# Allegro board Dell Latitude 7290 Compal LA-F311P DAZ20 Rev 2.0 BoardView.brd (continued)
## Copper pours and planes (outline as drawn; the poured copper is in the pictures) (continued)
+BL_PWR_SRC on TOP (solid shape): 58.13,133.11 59.02,133.11 59.27,132.85 60.79,132.85 60.96,132.69 60.96,131.8 60.4,131.24 59.08,131.24 58.29,132.03 57.73,132.03 57.71,132.05 57.21,132.05 56.98,132.28 56.58,132.28 56.4,132.46 56.4,133.6 56.67,133.87 57.36,133.87
+BL_PWR_SRC on BOTTOM (solid shape): 60.37,133.28 60.37,132 60.54,131.84 60.54,131.39 60.41,131.27 58.96,131.27 58.84,131.39 58.84,131.81 59.13,132.1 59.13,133.28 59.21,133.36 60.3,133.36
+CHARGER_SRC on TOP (solid shape): 47.05,79.39 48.24,79.39 48.24,76.84 48.45,76.63 50.72,76.63 51.31,76.03 51.31,71.76 49.19,69.63 47.09,69.63 46.77,69.31 46.77,68.74 46.71,68.68 46.27,68.68 46.27,72.81 45.75,73.33 45.75,79.88 45.81,79.95 46.49,79.95
+CHARGER_SRC on BOTTOM (solid shape): 46.95,84.49 47.2,84.38 47.45,84.49 49.48,84.49 49.71,84.26 49.71,81.35 49.44,81.07 48.54,81.07 48.53,81.06 48.31,81.06 48,80.75 48,80.74 47.89,80.63 47.89,79.67 48.23,79.33 48.23,76.95 49.6,75.58 49.6,70.84 49.07,70.3 46.64,70.3 46.41,70.53 46.41,71.98 45.77,72.62 45.77,80.47 46.46,81.16 46.46,81.7 46.48,81.72 47.01,81.72 47.01,81.72 47.01,82.46 47.01,82.47 46.47,82.47 46.46,82.47 46.46,82.91 46.47,82.91 47.01,82.91 47.02,82.92 47.02,83.65 47,83.66 46.48,83.66 46.47,83.67 46.47,84.37 46.58,84.49
+DC_IN on TOP (solid shape): 46.51,121.3 46.51,119.77 46.89,119.39 46.89,118.5 45.36,116.98 45.24,116.98 45.11,117.1 45.11,117.16 44.53,117.74 44.47,117.74 44.22,117.99 44.22,118.12 44.6,118.5 44.6,118.58 44.6,119.31 44.63,119.31 44.63,120.08 44.6,120.08 44.6,120.23 44.63,120.23 44.63,120.99 44.6,120.99 44.6,121.3 44.98,121.68 46.12,121.68
+DC_IN on BOTTOM (solid shape): 46.89,123.67 46.89,121.11 47.33,120.66 47.33,118.5 47.26,118.43 43.13,118.43 42.95,118.48 42.77,118.43 41.82,118.43 41.74,118.5 41.74,119.26 41.81,119.33 42.51,119.33 42.89,119.71 42.89,121.17 43.39,121.68 43.71,121.68 44.37,122.34 44.37,123.63 44.71,123.98 46.57,123.98
+DC_IN on IN3: 41.68,80.4 42.16,80.4 42.72,79.84 42.72,79.22 38.58,75.08 38.58,64.02 35.59,61.03 34.74,61.03 34.57,61.2 34.57,61.72 34.84,61.99 34.98,61.99 37.83,64.83 37.83,76.54
+DC_IN_SS on BOTTOM (solid shape): 52.78,119.04 52.78,117.33 52.63,117.18 49.58,117.18 48.94,116.55 48.94,113.24 48.77,113.07 44.59,113.07 44.42,113.12 44.26,113.07 44.19,113.07 43.89,113.37 43.89,115.4 44.17,115.68 44.17,116.32 44.83,116.98 44.83,117.59 45.01,117.77 47.55,117.77 48.97,119.19 52.63,119.19
+DCIN_JACK on BOTTOM (solid shape): 41.91,121.74 41.93,121.74 41.95,121.72 42.01,121.71 42.06,121.7 42.11,121.69 42.31,121.49 42.31,119.84 42.06,119.58 41.74,119.58 41.49,119.33 41.49,118.44 41.3,118.25 39.27,118.25 39.08,118.06 36.66,118.06 36.47,118.25 36.47,118.82 39.78,118.82 39.78,118.77 39.79,118.71 39.8,118.66 39.83,118.61 39.86,118.57 39.89,118.53 39.93,118.5 39.98,118.47 40.03,118.45 40.08,118.44 40.14,118.44 40.19,118.44 40.24,118.45 40.29,118.47 40.34,118.5 40.38,118.53 40.41,118.57 40.44,118.61 40.47,118.66 40.48,118.71 40.49,118.77 40.49,118.82 40.48,118.87 40.47,118.92 40.44,118.97 40.41,119.02 40.38,119.05 40.34,119.09 40.29,119.11 40.24,119.13 40.19,119.15 40.14,119.15 40.08,119.15 40.03,119.13 39.98,119.11 39.93,119.09 39.89,119.05 39.86,119.02 39.83,118.97 39.8,118.92 39.79,118.87 39.78,118.82 36.47,118.82 36.47,121.4 36.82,121.74 41.84,121.74
+EC_DEBUG_VCC on BOTTOM (solid shape): 290.28,126.58 291.32,126.58 291.4,126.5 291.4,126.26 291.3,126.15 289.98,126.15 289.74,126.39 289.19,126.39 288.84,126.75 288.84,127.41 288.88,127.46 289.41,127.46
+EDP_VDD on TOP (solid shape): 67.97,126.76 67.97,124.92 67.65,124.6 66.7,124.6 66.52,124.78 66.52,125.61 65.86,126.27 65.86,127.71 67.02,127.71
+LCDVDD on TOP (solid shape): 69.81,134.5 69.81,132.66 68.73,131.58 66.25,131.58 66.19,131.52 66.19,130.95 65.95,130.7 65.95,128.03 65.68,127.77 65.68,127.46 65.11,127.46 65.11,126.95 65.68,126.95 65.68,126.69 64.6,126.69 64.41,126.88 64.41,131.14 64.79,131.51 64.79,132.39 64.9,132.5 64.92,132.5 65.47,133.04 65.94,133.04 66.38,133.49 66.38,134.57 66.57,134.76 69.56,134.76
+LCDVDD on BOTTOM (solid shape): 66.38,133.3 66.38,132.03 66.57,131.84 66.57,131.2 66.13,130.76 66.13,129.74 66,129.61 64.79,129.61 64.67,129.74 64.67,131.58 64.92,131.84 65.43,131.84 65.62,132.03 65.62,133.3 65.68,133.36 66.32,133.36
+PBATT on TOP (solid shape): 177.47,58.59 177.47,55.73 177.51,55.69 177.51,55.25 177.46,55.19 175.09,55.19 174.97,55.32 174.97,56.46 174.52,56.91 171.98,56.91 170.79,58.1 170.03,58.1 169.86,58.27 169.86,59.85 170.2,60.19 170.2,60.21 170.78,60.78 175.28,60.78
+PWR_SRC on TOP (solid shape): 178.63,51.09 178.9,51.02 179.16,51.09 183.55,51.09 183.73,50.91 183.73,49.52 183.51,49.3 180.24,49.3 180.08,49.45 180.08,50.21 179.83,50.46 178.36,50.46 178.28,50.53 178.28,50.99 178.39,51.09
+PWR_SRC on TOP (solid shape): 44.54,123.33 44.54,121.93 44.28,121.68 41.89,121.68 41.89,122.24 41.82,122.48 41.64,122.67 41.6,122.74 41.63,122.83 41.81,123.01 43.46,123.01 43.9,123.45 44.41,123.45
+PWR_SRC on TOP (solid shape): 151.34,82.84 151.34,82.3 151.36,82.29 151.82,82.29 151.82,79.83 151.72,79.73 150.74,79.73 149.82,80.64 149.82,81.87 149.73,81.97 149.73,82.24 149.77,82.29 150.28,82.29 150.29,82.29 150.29,82.84 150.29,82.84 150.54,82.84 150.54,82.3 150.55,82.29 151.07,82.29 151.08,82.3 151.08,82.84 151.09,82.84 151.34,82.84
+PWR_SRC on TOP (solid shape): 166.22,54.49 167.04,53.67 170.9,53.67 171.22,53.35 171.22,52.41 170.69,52.41 170.67,52.39 170.65,52.38 170.34,52.03 170.65,51.68 170.67,51.67 170.69,51.65 171.14,51.65 171.17,51.62 171.17,50.19 170.84,49.86 164.74,49.86 164.43,50.18 164.43,50.6 164.34,50.68 161.44,50.68 161.31,50.81 161.31,51.17 161.45,51.3 164.03,51.3 164.26,51.53 164.26,54.52 164.38,54.64 164.38,54.64 164.56,54.82 165.89,54.82
+PWR_SRC on TOP (solid shape): outline of 174 points within 57.94,58.35 75.26,81.54
+PWR_SRC on BOTTOM (solid shape): 181.36,50.94 183.9,50.94 184,50.84 184,49.84 184.25,49.59 184.25,49.54 184.05,49.34 180.16,49.34 179.98,49.52 179.98,50.31 180.62,50.94 181.36,50.94
+PWR_SRC on BOTTOM (solid shape): 39.01,130.57 39.01,129.75 38.75,129.13 39.36,128.85 39.39,128.86 39.74,128.5 42.85,128.5 43.54,127.82 43.54,122.07 43.46,121.99 41.94,121.99 41.84,122.09 41.85,122.12 41.86,122.29 41.81,122.46 41.81,126.31 41.52,126.6 39.3,126.6 39.14,126.76 39.14,127.52 37.87,128.79 37.87,130.5 38.06,130.69 38.89,130.69
+PWR_SRC on BOTTOM (solid shape): outline of 2007 points within 57.44,49.86 169,82.82
+PWR_SRC on IN1: 182.47,49.49 182.32,49.34 173.2,49.34 172.39,50.15 170.97,50.15 170.15,49.34 164.82,49.34 164.36,49.79 164.36,52.77 164.46,52.87 177.52,52.87 177.53,52.86 181.53,52.86 182.47,51.91
+PWR_SRC on IN2: 41.87,122.31 42,122.44 43.33,122.44 44.28,121.49 44.28,120.34 44.16,120.22 43.39,120.22 41.87,121.74
+PWR_SRC on IN2: 57.23,117.18 56.55,117.86 56.55,118.64 56.23,118.95 56.23,119.64 56.59,120 57.55,120 58.14,119.42 58.14,118.57 58.65,118.05 58.65,117.46 58.37,117.18
+PWR_SRC on IN4: 57.2,118.3 58.47,118.3 58.88,117.89 58.88,115.93 58.47,115.53 57.42,115.53 56.84,116.11 56.84,117.95
+PWR_SRC on IN4: 62.42,72.41 62.42,70.5 62.61,70.31 62.61,61 62.32,60.72 60.85,60.72 60.35,61.22 60.35,66.54 59.42,67.47 59.42,69.62 58.6,70.45 58.6,77.89 61.73,81.03 71.7,81.03 71.91,80.83 71.91,78.04 70.55,76.68 63.98,76.68 63.72,76.42 63.72,73.69 62.44,72.41
+PWR_SRC on IN4: 172.33,49.98 171.77,49.93 171.2,49.98 170.98,49.46 170.96,49.38 170.88,49.34 164.54,49.34 164.36,49.52 164.36,51.76 164.68,52.08 177.56,52.08 179.19,50.45 182.33,50.45 182.47,50.3 182.47,49.49 182.32,49.34 172.65,49.34 172.57,49.38 172.56,49.46
+PWR_SRC_AC on TOP (solid shape): outline of 120 points within 43.35,81.94 48.85,86.53
+PWR_SRC_AC on BOTTOM (solid shape): outline of 176 points within 41.37,76.77 46.84,85.78
+REGCTL_PNP10 on TOP (solid shape): 246.58,123.43 246.58,122.08 246.91,121.75 246.91,121.09 246.78,120.97 246.3,120.97 246.18,121.09 246.18,121.52 246.3,121.7 246.25,121.91 246.25,122.24 246.38,122.36 246.38,123.43 246.43,123.48 246.53,123.48
+REGCTL_PNP10 on BOTTOM (solid shape): 252.2,125.35 252.2,124.24 251.65,123.68 250.89,123.68 250.54,124.03 250.54,125.28 250.68,125.42 252.13,125.42
+REGCTL_PNP10 on IN4 (solid shape): 251.66,124.38 251.66,123.64 250.58,122.57 247.86,122.57 247.1,121.8 247.1,121.04 246.91,120.85 246.15,120.85 245.83,121.17 245.83,122.57 247.35,124.08 250.22,124.08 250.8,124.67 251.36,124.67
+RTC_CELL_PCH on TOP (solid shape): outline of 333 points within 119.62,89.76 124.68,97.81
+SDC_IN on TOP (solid shape): 52.35,111.14 52.35,109.48 52.03,109.17 50.25,109.17 50.06,109.36 50.06,109.93 49.87,110.12 48.79,110.12 48.66,109.99 48.66,109.36 47.2,109.36 47.14,109.42 47.14,111.2 47.97,112.02 51.46,112.02
+SDC_IN on TOP (solid shape): 45.64,81.19 46,80.83 46.35,81.19 46.35,81.72 46.9,81.72 47.03,81.6 51.05,81.6 51.33,81.32 51.33,80.38 51.28,80.33 50.69,80.37 50.5,79.81 50.49,79.71 50.4,79.67 47.17,79.67 46.61,80.24 45.16,80.24 45.02,80.38 45.02,81.66 45.08,81.72 45.64,81.72
+SDC_IN on BOTTOM (solid shape): 52.75,116.4 52.75,116.39 52.75,111.71 51.01,109.97 51.01,105.23 47.71,105.23 47.69,105.25 47.69,106.8 47.42,107.07 46.23,107.07 45.74,106.59 45.21,106.59 44.98,106.82 44.98,107.63 45.21,107.86 46,107.86 46.23,108.09 46.23,108.6 45.97,108.85 44.91,108.85 44.7,108.65 44.04,108.65 44.04,109.18 44.12,109.26 45.83,109.26 46.06,109.48 46.06,110.06 46.44,110.44 46.44,111.2 46.23,111.42 46.23,112.32 46.32,112.41 48.73,112.41 49.31,112.98 49.31,116.53 49.33,116.56 52.75,116.56
+SDC_IN on IN3: 45.15,78.7 42.49,81.36 42.49,90.5 42.77,90.86 42.62,91.3 42.58,91.37 42.62,91.45 42.78,91.89 42.49,92.25 42.49,95.67 42.58,95.96 42.49,96.24 42.49,99.5 42.52,99.51 42.83,99.83 42.75,100.26 42.85,100.6 42.69,100.91 42.75,101.31 42.49,101.61 42.49,107.98 42.53,108.06 42.61,108.08 43.18,108.56 42.61,109.03 42.53,109.05 42.49,109.13 42.49,109.38 43.23,110.12 43.29,110.1 43.29,110.09 43.31,110.05 43.29,110.01 43.28,110.01 43.55,109.16 43.98,109.94 43.96,110.01 43.99,110.07 44.13,110.41 43.97,110.82 44,110.89 45.33,112.21 45.35,112.21 45.67,112.34 45.83,112.64 45.84,112.69 50.87,112.69 51.55,112.01 51.55,96.06 51.55,96.05 51.55,95.3 51.56,95.3 51.56,91.49 51.85,91.2 51.85,85.48 54.24,83.08 54.24,80.42 52.53,78.7
+SDC_IN on VCC: 46.87,59.7 40.92,65.65 40.92,76.44 38.5,78.86 38.5,80.8 38.74,81.04 48.85,81.04 49.91,82.1 50.33,82.1 51.08,81.35 51.08,75.6 54.63,72.04 54.63,72.03 55.05,71.62 55.05,71.52 52.73,69.2 52.73,59.83 52.6,59.7
+SDREG2 on TOP (solid shape): 279.07,66.88 278.34,66.88 277.77,66.3 277.77,66.23 277.72,66.18 276.96,66.18 276.88,66.25 276.88,66.33 276.93,66.38 277.09,66.38 277.95,67.24 279.07,67.24
+TBT_SVR_IND on BOTTOM (solid shape): 23.25,109.88 23.25,107.64 23.19,107.46 23.24,107.28 23.25,107.27 23.25,107.18 23.35,107.07 23.35,106.92 23.7,106.58 23.7,105.83 23.72,105.8 23.72,105.8 24.06,105.45 24.06,104.54 24.11,104.5 24.11,104.24 24.03,104.15 23.97,104.15 23.93,104.13 23.92,104.13 23.87,104.09 23.79,104 23.79,103.85 23.74,103.8 23.52,103.8 23.44,103.87 23.44,104.05 23.37,104.13 23.37,104.58 23.08,104.86 22.68,104.86 22.36,105.18 22.36,106.06 22.23,106.18 21.74,106.18 21.61,106.31 21.61,109.89 21.72,109.99 23.14,109.99
+TBTA_VBUS on TOP (solid shape): 23.36,116.7 23.36,112.79 23.22,112.66 20.73,112.66 19.52,113.87 16.79,113.87 16.41,114.25 16.41,116.6 16.72,116.91 23.14,116.91
+TBTA_VBUS on TOP (solid shape): 7.29,108.57 8.38,108.57 8.47,108.66 9.76,108.66 9.85,108.57 9.85,108.24 9.78,108.16 8.43,108.16 8.36,108.24 7.16,108.24 7.09,108.16 6.4,108.16 6.27,108.29 6.27,108.67 6.45,108.85 7.01,108.85
+TBTA_VBUS on TOP (solid shape): 7.14,106.06 8.38,106.06 8.47,106.14 9.5,106.14 9.57,106.07 9.57,105.73 9.5,105.65 8.43,105.65 8.34,105.74 7.18,105.74 6.88,105.45 6.42,105.45 6.3,105.57 6.3,106.03 6.42,106.16 7.03,106.16
+TBTA_VBUS on BOTTOM (solid shape): 9.67,105.88 9.98,105.88 10.06,105.8 10.06,104.92 9.86,104.72 9.61,104.72 8.49,105.84 8.49,106.07 8.55,106.13 9.43,106.13
+TBTA_VBUS on IN2: 7.77,109.97 7.78,110.01 7.78,110.84 7.77,110.88 7.77,112.91 8.79,113.93 10.76,113.93 13.11,113.83 14.75,115.51 15.84,116.6 21.61,116.6 22.19,116.03 22.19,113.42 21.8,113.04 18.69,113.04 15.45,109.8 11.33,109.8 11,109.48 10.99,109.47 10.87,109.39 10.79,109.27 10.79,109.26 10.63,109.1 10.63,108.25 10.54,108.01 10.63,107.78 10.63,105.87 10.18,105.42 6.44,105.42 6.32,105.54 6.32,106 6.44,106.12 7.07,106.12 7.26,106.31 7.26,107.96 7.07,108.15 6.5,108.15 6.32,108.33 6.32,108.99 6.56,109.23 7.2,109.23 7.77,109.8
+TBTA_VBUS on VCC: 7.62,105.29 7.5,105.42 6.48,105.42 6.35,105.55 6.17,105.55 6.17,111.63 5.19,113.04 3.52,112.64 1.42,112.64 1.42,114.59 2.27,115.01 2.62,115.9 2.62,117.08 9.73,117.08 9.73,116.5 12.05,114.18 14.37,116.5 14.37,117.08 22.12,117.08 22.12,116.87 22.38,116.62 22.38,114.42 22.02,114.06 20.87,114.06 16.66,109.84 16.66,108.57 16.43,108.34 12.75,108.34 9.7,105.29
+TBTA_VBUS_1 on TOP (solid shape): 29.11,121.18 29.11,118.86 29.41,118.56 29.41,116.28 29.96,116.28 29.96,115.83 29.42,115.83 29.42,115.08 29.96,115.08 29.96,114.63 29.42,114.63 29.42,112.97 29.36,112.91 27.03,112.91 26.78,112.66 25.87,112.66 25.76,112.78 25.76,113.38 25.63,113.51 24.11,113.51 24.03,113.59 24.03,116.69 24.2,116.86 25.54,116.86 26.12,117.44 26.12,121.04 26.31,121.23 29.06,121.23
+TBTA_VBUS_1 on BOTTOM (solid shape): 29.82,85.78 29.82,84.97 29.83,84.93 29.85,84.88 29.85,84.63 30.6,83.88 30.6,83.36 30.57,83.32 30.38,83.32 30.25,83.2 30.25,82.92 30.14,82.81 29.87,82.81 29.81,82.88 29.81,83.2 29.68,83.32 29.42,83.32 29.36,83.39 29.36,83.58 29.1,83.84 28.82,83.84 28.12,84.54 28.12,84.68 27.78,85.02 27.76,85.07 27.73,85.11 27.49,85.35 27.49,86.02 27.71,86.24 27.82,86.24 27.82,86.36 27.84,86.37 29.23,86.37
+TBTA_VBUS_1 on BOTTOM (solid shape): 20.31,75.74 20.31,74.06 19.98,73.73 18.06,73.73 17.93,73.86 17.93,73.92 17.61,74.24 16.72,74.24 16.22,74.75 16.22,75.61 19.34,75.61 19.34,75.56 19.36,75.51 19.37,75.46 19.4,75.41 19.43,75.37 19.47,75.34 19.52,75.3 19.57,75.28 19.62,75.27 19.67,75.26 19.72,75.26 19.78,75.27 19.83,75.28 19.87,75.3 19.92,75.34 19.96,75.37 19.99,75.41 20.02,75.46 20.04,75.51 20.05,75.56 20.05,75.61 20.05,75.67 20.04,75.72 20.02,75.77 19.99,75.82 19.96,75.86 19.92,75.89 19.87,75.92 19.83,75.95 19.78,75.96 19.72,75.97 19.67,75.97 19.62,75.96 19.57,75.95 19.52,75.92 19.47,75.89 19.43,75.86 19.4,75.82 19.37,75.77 19.36,75.72 19.34,75.67 19.34,75.61 16.22,75.61 16.22,75.64 16.66,76.08 19.96,76.08
+TBTA_VBUS_1 on IN2: 23.77,75.84 22.45,75.84 22.45,75.84 18.95,75.84 18.72,76.07 17.66,76.07 17.55,75.96 17.55,74.14 20.72,70.97 25.9,70.97 27.46,72.52 27.46,74.08 28,74.62 28.51,74.62 33.97,80.09 33.97,81.99 35.03,83.05 35.03,84.1 34.12,85.01 30.74,85.01 29.13,86.63 27.9,86.63 26.85,85.57 26.85,84.57 25.91,83.63 25.91,82.34 24.74,81.18 24.74,77.23 24.02,76.51 24.02,76.09
+TBTA_VBUS_1 on IN3: 16.08,75.16 11.42,79.82 11.42,94.6 10.5,95.52 10.5,99.46 7.89,102.07 7.89,111.1 10.41,113.62 13.15,113.62 16.61,117.08 24.6,117.08 25.22,117.24 25.7,117.67 28.14,117.67 28.95,116.87 28.95,114.67 26.51,112.23 21.69,112.23 21,111.54 21,109.41 17.44,105.84 17.44,98.25 19.16,96.53 19.16,93.4 18.94,93.17 18.94,92.68 20.25,91.36 20.25,74.39 19.87,74.01 17,74.01 16.08,74.94
+USB_EX2_PWR on TOP (solid shape): 19.65,67.45 19.65,65.35 15.64,65.35 15.33,65.67 15.33,67.19 15.71,67.57 19.52,67.57
+USB_EX2_PWR on BOTTOM (solid shape): 20.09,58.11 20.09,56.4 20.31,56.18 20.31,55.23 20.19,55.12 18.58,55.12 18.25,55.45 18.25,57.92 18.5,58.18 20.03,58.18
+USB_EX2_PWR on IN2: 17.93,64.78 17.93,55.76 18.18,55.51 19.65,55.51 19.96,55.83 19.96,67 19.52,67.45 15.77,67.45 15.33,67 15.33,65.73 15.71,65.35 17.36,65.35
+UZ12_TPM on BOTTOM (solid shape): 162.85,115.96 162.85,115.45 162.84,115.45 162.08,114.69 162.08,112.47 161.69,112.09 160.76,112.09 160.69,112.15 160.69,113.26 161.16,113.73 161.16,115.3 161.21,115.35 161.21,116.05 161.31,116.15 162.66,116.15
+UZ12_VHIO on BOTTOM (solid shape): 163.16,107.85 163.16,107.48 163.19,107.45 163.19,107.4 163.24,107.4 163.39,107.25 163.39,106.18 163.16,105.94 163.16,104.89 163.11,104.89 163.11,104.3 163.06,104.25 162.36,104.25 162.34,104.27 162.34,105.17 162.38,105.2 162.38,105.97 162.19,106.15 161.93,106.15 161.55,106.53 161.55,107.35 162.23,108.03 162.98,108.03
+VCHGR on TOP (solid shape): 176.9,54.53 176.9,52.72 176.89,52.71 176.89,51.44 176.78,51.32 174.1,51.32 173.87,51.09 172.29,51.09 172.24,51.14 172.24,51.67 172.78,51.67 173.14,52.03 172.78,52.39 172.24,52.39 172.24,53.48 172.49,53.73 174.52,53.73 174.78,53.99 174.78,54.56 174.9,54.68 176.74,54.68
+VCHGR on BOTTOM (solid shape): 176.87,52.29 176.87,51.37 176.78,51.28 175.22,51.28 175.19,51.24 174.9,51.24 174.7,51.44 174.7,52.06 175.11,52.47 176.69,52.47
+VHDMI_VCC on TOP (solid shape): 14.85,89.58 15.14,89.58 15.15,89.58 15.5,89.58 15.7,89.38 15.7,88.48 15.76,88.42 15.76,88.39 15.78,88.39 15.92,88.25 16.43,88.25 16.5,88.17 16.5,87.6 16.47,87.56 15.9,87.56 15.81,87.65 15.81,87.84 15.7,87.96 15.7,87.98 15.66,87.98 15.56,88.09 14.69,88.09 13.59,89.19 12.88,89.19 12.7,89.37 12.7,89.93 13.1,90.33 14.1,90.33
+VHDMI_VCC on BOTTOM (solid shape): 12.62,97.06 12.62,96.93 12.62,96.93 12.62,94.85 12.58,94.77 12.49,94.75 12.16,94.68 12.04,94.36 12.02,94.28 11.94,94.24 11.28,94.24 11,93.97 9.97,93.97 9.66,94.27 9.66,95.07 10.6,96.01 10.6,96.98 10.83,97.21 12.47,97.21
+VHDMI_VCC on IN4: 12.57,89.22 13.35,89.22 14.08,88.49 15.73,88.49 16.02,88.78 16.02,94.04 13.77,96.29 9.87,96.29 9.68,96.11 9.68,94.25 10,93.93 12.54,93.93 13.01,93.47 13.01,91.48 12.36,90.84 12.36,89.43
BOOT1_ISL9538 on TOP (solid shape): 57.48,60.92 57.2,60.92 56.69,60.41 56.69,59.83 56.82,59.7 56.82,58.68 56.77,58.63 56.67,58.63 56.62,58.68 56.62,59.47 56.34,59.75 56.34,60.82 56.62,61.1 56.62,61.53 57.48,61.53
BOOT2_ISL9538 on TOP (solid shape): 61.11,56.4 60.48,56.4 60.2,56.68 59.21,56.73 58.16,56.73 58.11,56.78 58.11,56.88 58.16,56.93 60.12,56.93 60.48,57.29 61.11,57.29
BST_3V on BOTTOM (solid shape): 155.47,74.28 155.47,73.52 155.85,73.14 156.72,73.14 156.82,73.04 156.82,72.22 156.79,72.2 155.95,72.2 155.22,72.93 155.22,74.26 155.29,74.33 155.42,74.33
BST_5V on BOTTOM (solid shape): 185.95,54.47 185.95,53.96 185.98,53.96 186.97,52.97 186.97,52.04 186.87,51.95 185.91,51.95 185.89,51.97 185.89,53.49 185.7,53.68 185.7,54.44 185.77,54.52 185.9,54.52
BST_+1VALWP on TOP (solid shape): 158.03,88.17 158.03,87.32 157.98,87.27 157.7,87.27 157.44,87.02 157.44,86.22 157.12,85.89 156.99,85.89 156.88,86 156.88,88.25 156.92,88.29 157.91,88.29
BST_+1VALWP_C on TOP (solid shape): 159.28,89.5 159.28,88.84 158.37,88.84 158.37,88.77 157.03,88.77 156.89,88.91 156.89,89.53 157.01,89.64 159.14,89.64
BST_DDR on BOTTOM (solid shape): 63.33,66.75 62.7,66.75 62.7,68.84 63.33,68.84
CPU_B+ on TOP (solid shape): 55.68,80.72 55.68,80.4 55.66,80.38 55.15,80.38 55.13,80.36 55.13,79.86 55.14,79.84 55.68,79.84 55.68,79.84 55.68,79.59 55.68,79.58 55.22,79.58 55.22,79.59 55.15,79.59 55.13,79.57 55.13,79.07 55.14,79.06 55.66,79.06 55.68,79.03 55.68,78.3 55.95,78.03 55.95,74.1 55.69,73.84 52.06,73.84 51.84,74.05 51.84,79.19 52.28,79.63 52.3,79.63 52.45,79.66 52.57,79.76 52.65,79.79 52.73,79.76 53,79.63 53.35,79.78 53.43,79.74 53.86,79.65 54.04,80.05 54.04,80.63 54.19,80.78 55.62,80.78
CPU_B+ on TOP (solid shape): 54.02,107.95 57.8,107.95 57.86,107.89 57.86,106.79 57.73,106.66 56.76,106.66 56.73,106.63 56.73,103.73 57.2,103.26 58.11,103.26 58.28,103.1 58.28,100.88 58.27,100.87 58.27,100.5 58.32,100.46 58.32,97.71 58.27,97.66 57.19,97.66 57.13,97.72 57.13,99.1 57.07,99.16 55.5,99.16 55.28,99.38 55.28,101.06 55.32,101.14 55.41,101.15 55.88,101.56 55.3,101.76 55.26,101.75 55.23,101.76 55.03,101.97 55.03,101.98 54.95,102.06 54.57,102.06 54.56,102.07 54.39,102.07 54.34,102.11 54.27,102.15 54.26,102.15 53.33,103.08 53.33,104.4 53.42,104.5 53.42,104.99 53.43,105 53.43,107.01 53.43,107.02 53.43,107.16 53.27,107.32 52.82,107.32 52.76,107.38 52.76,108.21 52.86,108.31 53.65,108.31
CPU_B+ on BOTTOM (solid shape): 64.98,112.34 64.98,111.45 64.86,111.33 63.59,111.33 63.46,111.45 63.46,112.34 63.59,112.47 64.86,112.47
CPU_B+ on BOTTOM (solid shape): 54.02,107.95 57.82,107.95 57.82,106.63 56.42,106.63 56.29,106.5 56.29,105.85 56.15,105.7 55.06,105.7 54.8,105.44 54.8,103.15 55.01,102.94 57.39,102.94 57.68,103.22 58.16,103.22 58.27,103.12 58.27,100.51 58.32,100.46 58.32,97.67 58.29,97.64 57.18,97.64 57.11,97.71 57.11,98.99 56.92,99.18 56.22,99.18 56.13,99.27 56.13,100.3 56.58,100.75 56.58,101.54 56.33,101.79 55.74,101.79 55.66,101.87 55.65,101.86 55.08,101.86 54.76,102.18 53.49,102.18 53.36,102.31 53.36,104.46 53.42,104.51 53.42,107.17 53.34,107.25 53.34,107.25 53.28,107.31 52.83,107.31 52.76,107.38 52.76,108.21 52.86,108.32 53.65,108.32
CPU_B+ on BOTTOM (solid shape): 61.5,82.39 61.5,79.49 62.19,78.79 63.74,78.79 63.92,78.61 63.92,76.09 63.68,75.84 63.01,75.84 63.01,75.29 63.01,75.29 62.57,75.29 62.57,75.29 62.57,75.61 62.57,75.61 62.57,75.83 62.57,75.83 61.81,75.83 61.81,75.3 61.81,75.29 61.37,75.29 61.36,75.3 61.36,75.84 60.65,75.84 60.45,76.03 60.45,76.39 60.45,76.44 60.45,76.49 60.45,77.56 59.96,78.05 58.47,78.05 58.1,78.42 56.49,78.42 55.92,77.85 55.92,74.07 55.68,73.82 50.7,73.82 50.6,73.93 50.6,76.69 51,77.1 51.81,77.1 52.2,77.48 52.2,79.03 52.63,79.46 54.03,79.46 54.42,79.86 54.42,82.64 55.22,83.43 60.46,83.43
CPU_B+ on IN1 (solid shape): 58,102.7 58,100.72 58.31,100.41 58.31,97.95 57.99,97.63 57.34,97.63 57.14,97.83 57.14,98.37 56.15,99.35 56.15,102.65 56.46,102.96 57.74,102.96
CPU_B+ on IN1 (solid shape): 57.82,107.68 57.82,106.72 57.78,106.67 56.65,106.67 54.98,105 53.86,105 53.74,105.12 53.74,106.4 53.83,106.48 54.93,106.48 55.06,106.61 55.06,107.8 55.18,107.93 57.57,107.93
CPU_B+ on IN2 (solid shape): 57.82,107.68 57.82,105.71 57.44,105.34 57.44,104.58 58.23,103.8 58.23,100.53 58.31,100.44 58.31,97.96 57.98,97.63 56.89,97.63 56.21,98.31 56.21,102.32 55.92,102.62 54.13,102.62 53.74,103.01 53.74,106.4 53.83,106.48 54.91,106.48 55.06,106.63 55.06,107.8 55.18,107.92 57.58,107.92
CPU_B+ on IN3 (solid shape): 58.31,100.25 58.31,97.94 58.02,97.64 57.55,97.64 57,98.19 57,100.22 57.16,100.39 58.17,100.39
CPU_B+ on IN3 (solid shape): 57.66,102.96 57.66,101.84 57.58,101.76 56.27,101.76 56.12,101.91 56.12,102.69 56.53,103.1 57.52,103.1
CPU_B+ on IN3 (solid shape): 57.82,107.69 57.82,105.7 57.12,105 53.86,105 53.74,105.12 53.74,106.4 53.83,106.48 54.92,106.48 55.06,106.62 55.06,107.81 55.18,107.93 57.58,107.93
CPU_B+ on IN4 (solid shape): 58,102.7 58,100.63 58.31,100.32 58.31,97.84 58.1,97.63 56.96,97.63 56.15,98.44 56.15,102.65 56.46,102.96 57.74,102.96
CPU_B+ on IN4 (solid shape): 57.82,107.69 57.82,105.7 57.12,105 53.86,105 53.74,105.12 53.74,106.4 53.83,106.48 54.92,106.48 55.06,106.62 55.06,107.81 55.18,107.93 57.58,107.93
CPU_B+ on VCC: 51.59,81.56 50.82,82.32 50.82,95.92 51.97,97.06 51.97,99.09 52.73,99.85 52.73,108.36 56.64,112.28 64.69,112.28 64.79,112.17 64.79,108.96 62.13,106.29 62.13,100.83 58.82,97.53 58.82,82.25 58.83,82.25 58.83,72.16 58.66,71.99 55.4,71.99 51.59,75.81 ; 1 cut-out
EN_1.8VALW on BOTTOM (solid shape): 175.79,66.56 175.79,66.48 174.6,65.29 174.19,65.29 173.76,65.72 173.76,67.78 174.17,68.18
GPU_B+ on TOP (solid shape): 57.02,88.62 57.75,88.62 57.86,88.52 57.86,84.22 58.05,84.02 58.05,78.75 57.86,78.56 55.86,78.56 55.82,78.6 55.82,79.17 55.79,79.19 55.27,79.19 55.27,79.19 55.27,79.44 55.27,79.45 55.81,79.45 55.82,79.46 55.82,79.98 55.81,79.99 55.29,79.99 55.27,80 55.27,80.24 55.27,80.24 55.8,80.24 55.82,80.26 55.82,80.86 55.66,81.02 52.33,81.02 52.12,81.23 52.12,84.51 53.32,85.72 53.32,88.5 53.45,88.63 57.02,88.63
GPU_B+ on BOTTOM (solid shape): 57.87,88.51 57.87,87.36 57.76,87.25 56.49,87.25 56.34,87.1 56.34,86.45 56.28,86.39 55.42,86.39 54.94,85.91 54.94,83.42 54.79,83.27 52.52,83.27 52.27,83.51 52.27,84.65 53.3,85.67 53.3,88.48 53.45,88.64 57.75,88.64
GPU_B+ on IN1 (solid shape): 57.87,88.49 57.87,86.47 57.7,86.31 55.42,86.31 55.12,86.61 55.12,88.41 55.27,88.56 57.79,88.56
GPU_B+ on IN2 (solid shape): 57.85,88.5 57.85,86.27 54.83,83.25 52.64,83.25 52.28,83.61 52.28,84.36 55.09,87.17 55.09,88.4 55.23,88.55 57.8,88.55
GPU_B+ on IN3 (solid shape): 57.87,88.44 57.87,87.06 57.55,86.74 55.44,86.74 55.12,87.05 55.12,88.41 55.28,88.56 57.75,88.56
GPU_B+ on IN4 (solid shape): 57.85,88.44 57.85,86.27 54.83,83.25 52.64,83.25 52.28,83.61 52.28,84.36 55.09,87.17 55.09,88.4 55.23,88.55 57.74,88.55
GT_SNUB on TOP (solid shape): 63.78,87.89 63.78,85.93 63.52,85.67 61.68,85.67 61.62,85.74 61.62,87.64 61.94,87.96 63.71,87.96
GT_SW on TOP (solid shape): 66.44,87.83 66.44,86.18 66.38,86.12 64.57,86.12 64.31,86.37 64.31,88.07 64.41,88.17 66.1,88.17
GT_SW on BOTTOM (solid shape): 65.23,94.09 65.23,90.53 64.26,90.53 64.26,89.71 65.23,89.71 65.43,89.5 65.43,86.88 65.24,86.69 64.39,86.69 62.86,88.21 62.7,88.37 62.7,89.53 61.82,90.42 61.11,90.42 60.88,90.19 60.88,89.76 60.81,89.69 60.03,89.69 59.95,89.76 59.95,91.01 59.89,91.07 56.16,91.07 55.97,91.26 55.97,92.09 56.33,92.45 60.33,92.45 61.05,93.17 61.05,94.17 61.34,94.46 64.86,94.46
HDMI_OB on TOP (solid shape): 17.17,84.14 17.17,83.89 17.15,83.76 17.17,83.63 17.17,83 17.15,82.87 17.17,82.74 17.17,82.11 17.15,81.98 17.17,81.85 17.17,81.22 17.15,81.09 17.17,80.96 17.17,80.36 17.17,80.35 17.15,80.21 17.17,80.07 17.17,80.06 17.17,79.55 17.17,79.54 17.15,79.4 17.17,79.26 17.17,79.25 17.17,78.75 17.15,78.61 17.17,78.48 17.17,77.92 17.15,77.79 17.17,77.66 17.17,77.54 17.03,77.4 16.41,77.4 16.29,77.52 16.29,84.14 16.48,84.33 16.98,84.33
IA_SNUB1 on TOP (solid shape): 60.49,113.49 60.49,111.28 59.72,110.52 58.07,110.52 57.96,110.62 57.96,111.49 58.06,111.58 58.89,111.58 59.29,111.99 59.29,113.47 59.32,113.52 59.42,113.63 60.35,113.63
IA_SNUB2 on TOP (solid shape): 63.6,96.59 63.6,94.73 63.49,94.61 62.85,94.61 62.8,94.66 62.8,95.28 62.18,95.9 61.49,95.9 61.36,96.02 61.36,96.99 61.52,97.14 63.05,97.14
IA_SW2 on BOTTOM (solid shape): 62.88,100.77 65.32,100.77 65.41,100.68 65.41,99.39 64.47,99.39 64.47,98.63 65.41,98.63 65.41,96.5 63.65,94.74 62.78,94.74 62.69,94.8 62.7,94.9 62.42,95.47 62.14,94.9 62.14,94.8 62.05,94.74 59.55,94.74 59.47,94.82 59.47,95.55 59.51,95.59 60.83,95.59 60.97,95.73 60.97,99.33 60.98,99.34 60.98,100.4 61.35,100.77 61.34,101.45 61.49,101.6 62.05,101.6
INT_SPK_L+ on TOP (solid shape): 279.61,24.08 280.12,24.08 280.12,22.36 279.61,22.36 279.49,22.49 279.49,22.81 278.53,23.76 278.53,24.65 279.04,24.65
INT_SPK_L+ on TOP (solid shape): 265.35,60.95 265.35,59.95 262.91,59.95 262.79,59.83 261.33,59.83 261.12,60.03 259.97,60.03 259.92,60.08 259.92,60.18 259.97,60.23 262.63,60.23 263.37,60.97 265.33,60.97
INT_SPK_L- on TOP (solid shape): 279.68,26.11 280.06,26.11 280.12,26.05 280.12,24.39 279.61,24.39 279.55,24.46 279.55,24.78 278.66,25.66 278.66,26.24 278.92,26.49 279.3,26.49
INT_SPK_L- on TOP (solid shape): 265.17,61.1 263.29,61.1 262.58,60.39 260.88,60.39 260.83,60.44 259.94,60.44 259.92,60.46 259.92,60.59 259.97,60.64 262.23,60.64 263.7,62.11 263.83,62.11 263.83,62.11 265.17,62.11
INT_SPK_R+ on TOP (solid shape): 280.12,21.47 280.12,20.33 278.85,20.33 278.73,20.46 278.73,21.54 278.92,21.73 279.87,21.73
INT_SPK_R+ on TOP (solid shape): 262.71,62.19 262.71,61.86 262.61,61.76 261.74,61.76 261.2,61.22 259.97,61.22 259.92,61.28 259.92,61.4 259.97,61.45 260.91,61.45 261.75,62.29 262.61,62.29
INT_SPK_R+ on IN1 (solid shape): 278.98,22.62 280,21.6 280,21.35 279.87,21.22 278.92,21.22 277.96,22.17 277.96,23.12 278.98,23.12
INT_SPK_R+ on IN1 (solid shape): 263.63,61.78 263.63,61.78 263.63,61.68 261.72,61.68 261.62,61.78 261.62,61.89 261.62,61.89 261.62,62.6 261.72,62.7 263.63,62.7
INT_SPK_R- on TOP (solid shape): 280.12,19.44 280.12,18.3 278.85,18.3 278.73,18.43 278.73,18.93 278.47,19.19 278.47,19.57 278.6,19.7 279.87,19.7
INT_SPK_R- on TOP (solid shape): 262.51,61.45 262.51,61.2 262.13,60.82 259.97,60.82 259.92,60.87 259.92,61 259.97,61.05 261.31,61.05 261.8,61.53 262.43,61.53
INT_SPK_R- on IN1 (solid shape): 279.49,20.27 279.49,19.38 279.3,19.19 278.6,19.19 278.41,19.38 278.41,20.65 278.6,20.84 278.92,20.84
INT_SPK_R- on IN1 (solid shape): 263.27,60.49 261.69,60.49 261.47,60.72 261.47,61.4 261.57,61.5 263.27,61.5
INT_SPKR_L+ on TOP (solid shape): 281.52,23.1 281.52,22.31 281.51,22.31 281.39,22.2 280.55,22.2 280.38,22.38 280.38,23.14 280.5,23.26 281.35,23.26
INT_SPKR_L+ on BOTTOM (solid shape): 283.11,22.31 283.08,22.29 281.96,22.29 281.89,22.21 281.13,22.21 281.02,22.31 281.02,23.18 281.15,23.3 283.11,23.3
INT_SPKR_L- on TOP (solid shape): 281.52,25.16 281.52,24.37 281.51,24.37 281.39,24.26 280.55,24.26 280.38,24.43 280.38,25.2 280.5,25.32 281.35,25.32
INT_SPKR_L- on BOTTOM (solid shape): 283.11,25.23 283.11,24.27 283.06,24.22 281.15,24.22 281.02,24.34 281.02,25.13 281.18,25.28 283.06,25.28
INT_SPKR_R+ on TOP (solid shape): 281.52,21.05 281.52,20.27 281.51,20.27 281.39,20.15 280.55,20.15 280.38,20.33 280.38,21.09 280.5,21.22 281.35,21.22
INT_SPKR_R+ on BOTTOM (solid shape): 283.61,21.09 283.61,20.2 283.55,20.14 281.2,20.14 281.01,20.33 281.01,21.16 281.14,21.28 283.42,21.28
INT_SPKR_R- on TOP (solid shape): 281.52,19.02 281.52,18.24 281.51,18.24 281.39,18.12 280.55,18.12 280.38,18.3 280.38,19.06 280.5,19.19 281.35,19.19
INT_SPKR_R- on BOTTOM (solid shape): 283.25,19.28 283.25,18.33 283.03,18.11 281.2,18.11 281.01,18.3 281.01,19.06 281.14,19.19 281.71,19.19 281.9,19.38 283.15,19.38
LG1_ISL9538 on TOP (solid shape): 42.6,69.12 42.6,67.48 42.37,67.25 41.73,67.25 41.58,67.41 41.58,69.09 41.69,69.21 42.52,69.21
LG1_ISL9538 on TOP (solid shape): 58.98,60.08 58.98,59.65 57.96,58.63 57.89,58.63 57.81,58.71 57.81,59.47 58.55,60.21 58.85,60.21
LG1_ISL9538 on IN4 (solid shape): 59.74,60.36 58.65,59.27 58.27,59.27 58.14,59.4 58.14,59.7 58.72,60.29 58.72,61.07 59.74,61.07
LG1_ISL9538 on IN4 (solid shape): 42.57,70.42 42.57,67.22 42.54,67.19 41.54,67.19 41.39,67.34 41.39,70.41 41.64,70.66 42.33,70.66
LG2_ISL9538 on TOP (solid shape): 60.12,58.76 60.12,58.43 60.02,58.33 59.61,58.33 59.23,57.95 58.16,57.95 58.11,58 58.11,58.1 58.16,58.15 58.95,58.15 59.64,58.84 60.04,58.84
LINE1_L on TOP (solid shape): 254.71,58.99 254.71,58.89 254.66,58.84 253.9,58.84 253.69,58.63 253.69,57.57 252.98,56.86 252.22,56.86 252.22,57.72 253.03,57.72 253.29,57.97 253.29,58.63 253.69,59.04 254.66,59.04
LINE1_R on TOP (solid shape): 254.74,59.4 254.74,59.29 254.66,59.22 253.64,59.22 253.13,58.71 253.13,58.18 253.01,58.05 252.17,58.05 252.17,58.94 252.96,58.94 253.47,59.45 254.68,59.45
LX1_ISL9538 on TOP (solid shape): 58.7,60.56 57.63,59.5 57.63,58.68 57.58,58.63 57.48,58.63 57.43,58.68 57.43,59.93 57.81,60.31 57.81,61.5 57.83,61.53 58.7,61.53
LX1_ISL9538 on TOP (solid shape): 45.63,68.58 46.35,67.86 46.81,67.86 47.21,67.46 47.21,64.77 46.21,63.77 45.91,63.77 45.91,63.77 43.55,63.77 42.96,64.35 42.96,72.71 45.63,72.71
LX1_ISL9538 on BOTTOM (solid shape): 46.11,71.78 46.11,70.44 47.18,69.37 47.18,64.71 46.22,63.76 42.91,63.76 42.24,64.43 42.24,71.84 42.56,72.16 45.72,72.16
LX1_ISL9538 on IN1 (solid shape): 48.04,67.09 48.04,66.24 47.89,66.09 46.38,66.09 46.26,66.21 46.26,67.18 46.41,67.33 47.81,67.33
LX1_ISL9538 on IN1 (solid shape): 59,61.15 59,60.75 57.83,59.58 57.6,59.58 57.48,59.7 57.48,59.7 57.48,60.06 57.73,60.31 57.73,61 57.96,61.22 58.93,61.22
LX2_ISL9538 on TOP (solid shape): 57.65,69.57 57.65,63.53 57.31,63.19 56.54,63.19 56.37,63.03 56.37,62.76 56.27,62.65 55.16,62.65 54.85,62.96 54.85,69.45 55.3,69.91 57.32,69.91
LX2_ISL9538 on TOP (solid shape): 61.11,57.62 60.3,57.62 60.2,57.72 59.66,57.72 59.49,57.54 58.16,57.54 58.11,57.59 58.11,57.69 58.16,57.75 59.23,57.75 59.69,58.2 60.2,58.2 60.48,58.48 61.11,58.48
LX2_ISL9538 on BOTTOM (solid shape): 56.32,69.92 56.99,69.92 57.14,69.77 57.14,69.63 57.57,69.2 57.57,65.57 57.39,65.39 54.3,65.39 53.95,65.74 53.6,65.74 53.47,65.77 53.33,65.74 51.53,65.74 51.47,65.81 51.47,70.06 51.72,70.32 55.92,70.32
LX_1.8VALW on BOTTOM (solid shape): 175.96,64.63 175.96,62.87 173.9,60.8 173.28,60.8 172.99,61.09 173,61.1 173,61.48 173.63,62.11 173.63,62.37 173.15,62.86 173.15,63.37 172.54,63.97 172.54,64.44 172.8,64.7 173.19,64.7 173.82,64.07 173.97,64.07 175.02,65.12 175.47,65.12
LX_1V_PRIM on BOTTOM (solid shape): 155.4,129.47 155.4,129.25 155.34,129.2 155.34,128.79 155.47,128.66 156.31,128.66 156.39,128.59 156.39,127.98 156.31,127.9 155.47,127.9 155.32,127.75 155.32,127.18 154.84,126.69 154.01,126.69 153.95,126.76 153.95,129.42 154.13,129.6 155.27,129.6
LX_1VS_VCCIO on BOTTOM (solid shape): 139.66,131.84 139.66,131.07 139.47,130.88 139.47,130.31 139.6,130.19 140.46,130.19 140.53,130.12 140.53,129.5 140.45,129.42 138.2,129.42 138.07,129.55 138.07,131.96 138.14,132.03 139.47,132.03
LX_3V on BOTTOM (solid shape): 153.34,74.61 153.34,74.48 153.24,74.38 153.24,73.77 153.08,73.62 152.63,73.62 152.25,74 152.25,74.39 152.53,74.67 153.27,74.67
LX_3V on BOTTOM (solid shape): 159.84,77.77 159.84,70.77 159.65,70.59 158.24,70.59 158.21,70.62 158.21,72.32 158.06,72.46 157.15,72.46 157.06,72.56 157.06,73.23 157,73.29 156.01,73.29 155.73,73.57 155.73,74.33 155.57,74.48 155.57,75.07 155.64,75.13 157.44,75.13 157.62,75.31 157.62,77.84 157.72,77.94 159.67,77.94
LX_3V on IN1 (solid shape): 153.41,74.48 153.69,74.34 153.98,74.48 154.93,74.48 155.22,74.33 155.51,74.48 157.02,74.48 157.12,74.38 157.12,73.67 157.02,73.57 152.58,73.57 152.25,73.9 152.25,74.38 152.35,74.48
LX_5V on TOP (solid shape): 188.62,53.54 185.73,53.54 185.6,53.57 185.46,53.54 183.09,53.54 182.6,54.03 182.6,54.35 182.8,54.56 183.6,54.56 183.79,54.37 186.33,54.37 187.16,55.19 188.62,55.19
LX_5V on BOTTOM (solid shape): 183.82,54.8 183.82,54.67 183.6,54.46 183.6,54.11 183.48,53.99 182.7,53.99 182.6,54.09 182.6,54.46 183.01,54.86 183.75,54.86
LX_5V on BOTTOM (solid shape): 190.84,56.82 190.84,53.54 189.17,51.87 187.27,51.87 187.13,52 187.13,53.06 186.21,53.99 186.21,54.52 186.05,54.67 186.05,55.26 186.12,55.32 187.92,55.32 188.17,55.57 188.17,57.01 190.65,57.01
LX_DDR on TOP (solid shape): 68.48,67.64 68.48,65.86 66.83,65.86 66.83,67.63 66.97,67.77 68.35,67.77
LX_DDR on BOTTOM (solid shape): 68.5,68.63 69.18,67.96 69.18,64.72 69.11,64.65 64.48,64.65 64.23,64.9 64.23,66.52 64.1,66.65 64.1,67.61 64.13,67.65 66.27,67.65 67.16,68.55 67.16,70.24 68.5,70.24
Net_95 on BOTTOM (solid shape): 282.2,39.4 278.1,39.4 278.1,47 282.2,47
Net_96 on BOTTOM (solid shape): 206.1,65.55 192,65.55 192,68.15 206.1,68.15
PBATT+_C on TOP (solid shape): 169.57,58.67 169.57,58.09 169.81,57.85 170.71,57.85 172.1,56.46 174.08,56.46 174.46,56.08 174.46,54.11 174.33,53.99 167.85,53.99 167.09,54.75 167.09,56.97 167.28,57.16 167.92,57.16 168.04,57.29 168.04,58.41 168.39,58.75 169.49,58.75
PBATT+_C on BOTTOM (solid shape): 174.14,58.11 174.14,57.48 172.24,55.57 168.84,55.57 168.04,56.37 168.04,58.94 168.43,59.32 170.08,59.32 171.35,60.59 171.66,60.59
RING2 on TOP (solid shape): 252.14,62.05 252.89,62.05 253.9,61.05 254.66,61.05 254.74,60.97 254.74,60.87 254.68,60.82 253.62,60.82 253.31,61.12 252.5,61.12 252.04,61.58 251.56,61.58 251.56,62.14 252.06,62.14
RING2 on BOTTOM (solid shape): 285.27,46.18 285.27,45.35 285.14,45.22 284.25,45.22 284.12,45.35 284.12,46.18 284.25,46.3 285.14,46.3
RING2 on IN4 (solid shape): 253.19,61.94 254.05,61.94 254.53,61.45 254.53,60.51 253.52,60.51 253.52,60.92 253.31,61.12 252.47,61.12 252.32,61.28 252.32,61.83 252.47,61.99 253.19,61.99
RING2 on IN4: 283.57,46.56 284.2,46.56 284.68,46.08 284.68,45.34 284.58,45.24 283.83,45.24 283.15,45.92 283.15,46.14
RING2_R on BOTTOM (solid shape): 292.43,46.07 292.43,45.73 292.61,45.56 292.61,45.27 293.58,45.27 293.71,45.14 293.71,43.57 295.74,41.54 295.74,40.71 294.79,40.71 294.47,41.03 294.47,41.22 292.7,43 292.7,44.47 292.58,44.58 292.58,44.6 292.28,44.89 292.27,44.89 292.05,45.11 292.05,45.12 291.45,45.73 291.43,45.73 291.12,46.05 289.2,46.05 288.5,45.35 285.52,45.35 285.52,46.18 285.58,46.24 287.42,46.24 288.25,47.06 291.43,47.06
SA_LGATE on BOTTOM (solid shape): 62.69,116.08 62.69,115.11 62.53,114.95 61.87,114.95 61.7,115.12 61.7,116.08 61.73,116.12 62.65,116.12
SA_LGATE on BOTTOM (solid shape): 69.04,116.92 69.04,116.44 68.67,116.07 67.94,116.06 67.84,116.17 67.84,116.6 67.84,116.6 67.84,117.01 68.04,117.21 68.75,117.21
SA_LGATE on IN4 (solid shape): 63.46,116.12 63.46,115.33 63.27,115.14 61.72,115.14 61.52,115.35 61.52,116.07 61.72,116.27 63.31,116.27
SA_LGATE on IN4: 68.12,117.3 68.29,117.3 69.01,116.57 69.01,116.37 68.56,115.92 68.52,115.92 68.47,115.87 67.71,115.87 67.5,116.08 67.5,116.68
SA_SNUB on TOP (solid shape): 67.66,115.61 66.64,114.58 66.64,113.68 65.62,113.68 65.62,115.33 66.5,115.33 67,115.83 67,116.55 67.66,116.55
SA_SW on TOP (solid shape): 69.29,115.76 69.29,113.68 68.3,113.68 68.3,115.76 68.45,115.91 69.14,115.91
SA_SW on TOP (solid shape): 63.5,113.47 63.5,113.09 62.89,112.48 62.25,112.48 62.25,113.35 62.86,113.35 63.12,113.6 63.37,113.6
SA_SW on BOTTOM (solid shape): 71.94,116.81 71.94,115.89 71.01,115.89 71.01,115.12 71.03,115.1 71.93,115.1 71.94,115.09 71.94,113.96 71.84,113.85 68.61,113.85 68.53,113.94 68.53,114.68 68.41,114.79 65.69,114.79 65.69,115.81 68.61,115.81 69.45,116.65 69.49,116.65 69.83,116.99 71.76,116.99
SA_UGATE on BOTTOM (solid shape): 59.13,113.9 59.33,113.7 60.32,113.7 60.4,113.63 60.4,113.35 59.85,112.8 58.87,112.8 58.71,112.96 58.71,113.75 58.86,113.9 59.13,113.9
SA_UGATE on BOTTOM (solid shape): 68.74,113.52 68.74,112.26 68.51,112.03 67.91,112.03 67.82,112.12 67.82,113.68 67.97,113.83 68.44,113.83
SA_UGATE on IN4 (solid shape): 68.81,113.01 68.81,112.19 68.5,111.88 67.52,111.88 67.42,111.98 67.42,112.7 67.92,113.2 68.62,113.2
SA_UGATE on IN4: 58.8,113.9 59.1,113.9 59.34,113.66 60.25,113.66 60.41,113.51 60.41,112.74 60.24,112.57 58.99,112.57 58.71,112.85 58.71,113.81
SLEEVE on TOP (solid shape): 252.42,60.95 253.24,60.95 253.54,60.64 254.68,60.64 254.74,60.59 254.74,60.49 254.66,60.41 252.98,60.41 252.93,60.46 251.66,60.46 251.56,60.56 251.56,61.25 252.12,61.25
SLEEVE on BOTTOM (solid shape): 285.27,44.97 285.27,44.14 285.14,44.02 284.25,44.02 284.12,44.14 284.12,44.97 284.25,45.1 285.14,45.1
SLEEVE on IN4 (solid shape): 253.26,60.82 253.26,59.73 252.25,59.73 252.25,60.79 252.37,60.92 253.16,60.92
SLEEVE on IN4: 283.37,45.06 284.52,45.06 284.73,44.86 284.73,43.94 284.57,43.78 283.34,43.78 283.02,44.1 283.02,44.72
SLEEVE_R on BOTTOM (solid shape): 289.46,44.14 291.36,44.14 291.49,44.02 291.49,43.44 293.52,41.41 293.52,40.85 293.38,40.71 291.95,40.71 291.81,40.85 291.81,41.41 290.09,43.13 288.44,43.13 287.42,44.14 286.23,44.14 286.15,44.06 286.15,43.49 286.05,43.39 285.64,43.39 285.52,43.51 285.52,45.03 285.58,45.1 288.5,45.1
SNB_+1VALWP on BOTTOM (solid shape): 155.24,85.17 155.24,83.38 154.91,83.05 153.75,83.05 153.39,83.41 153.39,85.26 153.44,85.31 155.11,85.31
SNU_DDR on TOP (solid shape): 68.48,69.86 68.48,68.53 66.95,68.53 66.83,68.65 66.83,70.5 67.84,70.5
SNUB_CHG1 on TOP (solid shape): 41.26,70.22 41.26,67.22 41.49,66.98 41.49,65.33 41.35,65.18 40.49,65.18 40.09,65.58 40.09,70.5 40.98,70.5
SNUB_CHG2 on TOP (solid shape): 52.86,64.65 53.11,64.4 53.55,64.4 53.55,62.75 52.41,62.75 51.97,63.19 51.97,65.42 52.86,65.42
SW_+1VALWP on TOP (solid shape): 155.04,85.79 155.04,85.62 154.99,85.57 153.34,85.57 153.17,85.74 153.17,86.01 153.39,86.22 154.61,86.22
SW_+1VALWP on TOP (solid shape): 160.69,87.19 160.69,85.5 160.59,85.4 159.77,85.4 159.28,84.9 159.07,84.9 159.05,84.93 158.68,84.93 158.62,84.87 158.35,84.87 158.12,85.1 157.31,85.1 157.24,85.18 157.24,85.78 157.6,86.15 157.6,86.99 157.72,87.1 158.23,87.1 158.37,87.24 158.37,88.19 158.38,88.2 159.26,88.2 159.26,88.31 159.57,88.31
SW_+1VALWP on BOTTOM (solid shape): 157.5,87.1 157.87,87.1 158.42,86.56 160.39,86.56 160.62,86.33 160.62,85.46 160.47,85.31 159.91,85.31 159.55,84.95 159.55,81.78 159.17,81.4 157.49,81.4 157.22,81.67 157.22,84.98 156.75,85.44 153.37,85.44 153.13,85.69 153.13,88.31 153.2,88.39 156.22,88.39
UG1_ISL9538 on TOP (solid shape): 48.66,68.97 48.66,63.66 48.64,63.65 47.76,63.65 47.51,63.89 47.51,68.97 47.7,69.16 48.47,69.16
UG1_ISL9538 on TOP (solid shape): 57.58,60.62 57.58,60.29 57.3,60.01 57.3,59.57 57.22,59.5 57.22,58.68 57.17,58.63 57.07,58.63 57.02,58.68 57.02,59.52 57,59.55 57,59.73 56.84,59.88 56.84,60.36 57.2,60.72 57.48,60.72
UG1_ISL9538 on IN1 (solid shape): 49.48,64.74 49.48,63.84 49.27,63.63 47.74,63.63 47.5,63.87 47.5,64.62 47.77,64.88 49.34,64.88
UG1_ISL9538 on IN1 (solid shape): 57.58,61.25 57.58,60.41 57.3,60.13 57.3,59.88 57.15,59.73 56.79,59.73 56.62,59.9 56.62,61.33 56.92,61.63 57.2,61.63
N16775517 on BOTTOM (solid shape): 66.67,68.91 66.67,68.57 66.06,67.96 64.1,67.96 64.08,67.96 64.08,68.82 64.11,68.84 64.72,68.84 64.86,68.71 65.65,68.71 65.96,69.01 66.57,69.01
N16783014 on TOP (solid shape): 158.09,80.05 158.09,79.13 158.06,79.13 158.06,78.57 158.09,78.57 158.09,78.51 157.99,78.41 157.76,78.41 156.68,77.33 156.68,77.13 156.2,76.66 155.85,76.66 155.73,76.78 155.73,77.8 156.11,78.18 156.11,79.51 156.19,79.59 156.71,79.59 156.76,79.55 156.76,79.53 156.77,79.47 156.81,79.39 156.81,79.35 157,79.16 157.39,79.16 157.46,79.23 157.46,79.5 157.47,79.57 157.46,79.64 157.46,80.02 157.59,80.15 157.99,80.15
N16783014 on BOTTOM (solid shape): 156.68,77.48 156.68,76.08 156.36,75.77 155.66,75.77 155.54,75.89 155.54,76.4 155.73,76.59 155.73,77.54 155.85,77.67 156.49,77.67
N16783223 on BOTTOM (solid shape): 187.14,57.17 187.14,56.22 186.89,55.97 186.1,55.97 186.05,56.02 186.05,56.6 186.33,56.88 186.33,57.16 186.52,57.35 186.96,57.35
N16784595 on BOTTOM (solid shape): 158.01,71.89 158.01,71.18 157.46,70.63 155.83,70.63 155.72,70.74 155.72,71.33 155.88,71.49 156.77,71.49 156.82,71.54 156.82,71.85 156.96,71.99 157.91,71.99
N16784799 on BOTTOM (solid shape): 188.25,51.33 188.25,50.59 187.99,50.34 185.96,50.34 185.75,50.55 185.75,51.09 185.91,51.26 186.84,51.26 186.84,51.42 188.16,51.42
N17370862 on BOTTOM (solid shape): 46,112.28 46,111.64 45.68,111.33 45.68,109.55 45.62,109.48 44.16,109.48 44.09,109.55 44.09,109.99 44.16,110.06 44.79,110.06 45.05,110.31 45.05,111.77 45.68,112.41 45.87,112.41
N17371029 on BOTTOM (solid shape): 48.66,121.23 48.64,121.21 48.61,121.18 48.49,120.88 48.66,120.61 48.66,119.24 47.83,118.4 47.62,118.4 47.52,118.5 47.52,119.21 47.7,119.39 47.7,120.8 47.27,121.23 47.27,121.87 48.66,121.87
N17802718 on TOP (solid shape): 48.89,103.36 48.89,102.66 48.47,102.24 48.29,102.24 47.91,101.86 44.7,101.86 44.58,101.99 44.58,102.55 44.6,102.55 44.6,102.56 47.39,102.56 48.3,103.47 48.78,103.47
N18278782 on TOP (solid shape): 58.67,62.32 56.62,62.32 56.62,62.95 58.67,62.95
N18617275 on TOP (solid shape): 159.65,84.75 159.65,83.81 159.56,83.73 157.25,83.73 157.18,83.8 157.18,84.41 157.26,84.5 158.53,84.5 158.8,84.77 159.62,84.77
N18988170 on BOTTOM (solid shape): 57.83,86.95 57.83,85.36 57.5,85.03 56.45,85.03 56.39,85.09 56.39,85.73 56.45,85.79 57.27,85.79 57.53,86.05 57.53,86.91 57.64,87.02 57.76,87.02
N18988180 on BOTTOM (solid shape): 57.57,84.36 57.57,83.75 57.44,83.63 55.18,83.63 55.11,83.7 55.11,84.39 55.21,84.48 57.44,84.48
N18988186 on BOTTOM (solid shape): 56.85,86.93 56.85,86.12 56.66,85.94 56.39,85.94 56.18,85.73 56.18,85.09 56.1,85.02 55.19,85.02 55.1,85.11 55.1,85.89 55.47,86.26 55.98,86.26 56.26,86.18 56.46,86.39 56.53,86.46 56.53,86.96 56.59,87.02 56.76,87.02
N18989156 on BOTTOM (solid shape): 56.06,100.47 56.06,100.41 56,100.36 56,99.53 55.96,99.33 56.06,99.15 56.09,99.12 56.12,99.09 56.23,98.99 56.78,98.99 56.84,98.92 56.84,98.73 56.76,98.65 55.9,98.65 55.69,98.86 55.69,99.58 55.54,99.73 54.93,99.73 54.79,99.87 54.79,100.72 54.91,100.84 55.68,100.84
N18989158 on BOTTOM (solid shape): 55.56,99.47 55.56,98.78 55.95,98.39 55.98,98.26 56.06,98.15 56.11,98.11 56.16,98.07 56.2,98.04 56.7,98.04 56.81,97.93 56.81,97.81 56.71,97.71 56.06,97.71 56.05,97.74 55.88,97.92 55.64,97.94 55.61,97.94 55.39,98.15 55.17,98.15 54.9,98.42 54.9,98.44 54.89,98.52 54.86,98.59 54.85,98.6 54.85,98.95 54.86,98.96 54.89,99.11 54.86,99.26 54.85,99.27 54.85,99.43 54.91,99.49 55.55,99.49
N18989160 on BOTTOM (solid shape): 54.16,100.69 54.16,98.57 54.07,98.48 53.57,98.48 53.49,98.57 53.49,100.69 53.55,100.76 54.09,100.76
N18989995 on BOTTOM (solid shape): 62.97,112.26 62.97,111.26 63.97,110.25 63.97,109.29 64.1,109.17 65.06,109.17 65.1,109.13 65.1,107.77 64.18,107.77 64.18,107.01 65.1,107.01 65.1,105.84 65.05,105.76 64.96,105.75 64.64,105.78 64.38,105.61 62.7,105.61 62.7,108.6 62.22,109.08 60.05,109.08 59.98,109.15 59.98,110.41 59.81,110.58 56.04,110.58 55.98,110.65 55.98,112.25 56.13,112.4 59.73,112.4 60.18,112.85 62.38,112.85
N18990006 on BOTTOM (solid shape): 56.79,106.39 56.79,105.53 56.55,105.3 56.23,105.3 56.23,105.29 56.17,105.29 55.96,105.09 55.96,104.48 55.88,104.4 55.07,104.4 54.97,104.5 54.97,105.33 55.21,105.58 56.2,105.58 56.23,105.6 56.24,105.6 56.48,105.84 56.48,106.39 56.55,106.46 56.72,106.46
N18990008 on BOTTOM (solid shape): 57.79,106.41 57.79,105.57 57.28,105.07 57.28,104.59 57.16,104.47 56.26,104.47 56.19,104.54 56.19,105.08 56.27,105.16 56.86,105.16 56.99,105.29 57,105.29 57.48,105.77 57.48,106.18 57.48,106.18 57.48,106.42 57.53,106.46 57.74,106.46
N18990010 on BOTTOM (solid shape): 57.22,103.79 57.22,103.14 57.18,103.09 55.09,103.09 55.01,103.17 55.01,103.79 55.03,103.81 57.2,103.81
N132000604 on TOP (solid shape): 62.51,56.4 61.87,56.4 61.87,58.51 62.51,58.51

Small or netless copper shapes (teardrops, artwork), in the pictures only: 240 on TOP, 175 on BOTTOM, 4 on GND1, 4 on GND2, 4 on GND3

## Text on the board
Ref Des/Silkscreen Bottom: H25 | A | M2X3 | 9 | H26 | GD1PC | REV:A01 | ALL RIGHT RESERVED | COPYRIGHT 2018 | PWA P/N: | PWB P/N: | 10 | 11 | FAN CABLE | SPEAKER | EDP CABLE | DIMM | DDR4 | CABLE | BATTERY | TP | USH | LED | DC-IN | RTC | 2 | 3 | 4 | 5 | 6 | 1 | 7 | 8 | BT | WLAN | LTE | WWAN
User.Comments: LA-F311P | 2018-01-08 | 2019-01-08 | DAZ20 | SF | GND | +VCC_GT | +VCC_SA | +VCC_CORE | +3.3V_ALW | +3.3V_RUN | +1.0VS_VCCIO | +3.3V_ALW_PCH | +1.0V_PRIM | +5V_ALW | +5V_RUN | GNDA
BODY_CENTER: L7 | L8 | L9 | L10 | TOP | GND1 | IN1 | IN2 | IN3 | VCC | GND3 | GND2 | IN4 | BOT
User.40: 7.7mil | 5mil | 4.9 / 4 | 3.7 / 3.5 | 4.7 / 3.5 | 4.1 / 3.5 | 4.5 / 5.2 | 3.7 / 5.2 | 4 / 3.5 | L9 | 8 / 4 | L8 | 10.5 /4.5 | 9.5 /5.5 | No Ref | L9-GND3 | L10-BOT | 100 ohm | Ref
User.43: FIGURE | SIZE | 8.0 | 16.0 | 20.0 | 22.0 | 28.0 | 35.0 | 39.0 | 102.0 | 122.0 | 126.0 | 134.0 | 138.0 | 150.0 | 30.0 | 31.0 | 43.0 | 45.0 | 63.0 | 65.0 | 71.0 | 91.0 | 47.0x20.0 | 55.0x24.0 | 55.0x28.0 | 57.0x24.0 | 63.0x24.0 | 63.0x31.0 | 67.0x28.0 | 94.0x28.0 | 94.0x43.0 | 37.0x31.0 | 106.0x91.0 | DRILL CHART: TOP to BOTTOM | ALL UNITS ARE IN MILS | TOLERANCE | +3.0/-3.0 | +2.0/-2.0 | PLATED | NON-PLATED | QTY | 5851 | 12 | 33 | 19 | 18 | 10 | 5 | 2 | 4 | 1 | 3 | 7
